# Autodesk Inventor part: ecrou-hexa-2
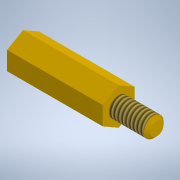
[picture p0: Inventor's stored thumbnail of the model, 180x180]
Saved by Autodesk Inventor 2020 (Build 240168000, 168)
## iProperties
Created: 2021-10
Part Number: ecrou-hexa-2
Material: Laiton, jaune doux
Document SubType Name: Modeling
Designer: bruno
Density: 8.47 g/cm^3
Appearance: Or
Mass: 2.22245 g
Surface Area: 4.994 cm^2
Volume: 0.262391 cm^3
Author: bruno
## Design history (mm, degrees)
sketch "Esquisse1"
  geometry: L1 (-2.887, 0)-(-1.443, 2.5); L2 (-1.443, 2.5)-(1.443, 2.5); L3 (1.443, 2.5)-(2.887, 0); L4 (2.887, 0)-(1.443, -2.5); L5 (1.443, -2.5)-(-1.443, -2.5); L6 (-1.443, -2.5)-(-2.887, 0); C1 r 1.5 at (0, 0); 2 further points
  constraints: 12 end point, 2 coincident, 1 centre point, 13 other
  dimensions: "d0" = 5 distance between parallel lines of L2 L5; "d1" = 3 diameter of C1
extrude "Extrusion1" new body sketch "Esquisse1" distance "d2" = 15; taper "d3" = 0 deg
feature "Filetage1" dims "d4" = 17, "d5" = 0
sketch "Esquisse2"
  geometry: C1 r 1.541 at (0, 0); 1 further point
  constraints: 1 centre point, 1 coincident
extrude "Extrusion2" join sketch "Esquisse2" distance "d6" = 6; taper "d7" = 0 deg
chamfer "Chanfrein1" distance "d8" = 0.5; stored, may be unused: second distance "d9" = 2, angle "d10" = 45 deg
feature "Filetage2" dims "d11" = 5.5, "d12" = 0
node "Solide1"
